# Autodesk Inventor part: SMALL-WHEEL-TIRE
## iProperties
Created: 2007-08
Part Number: SMALL-WHEEL-TIRE
Material: Rubber
Document SubType Name: Modeling
Density: 0.93 g/cm^3
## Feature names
1. Base1
